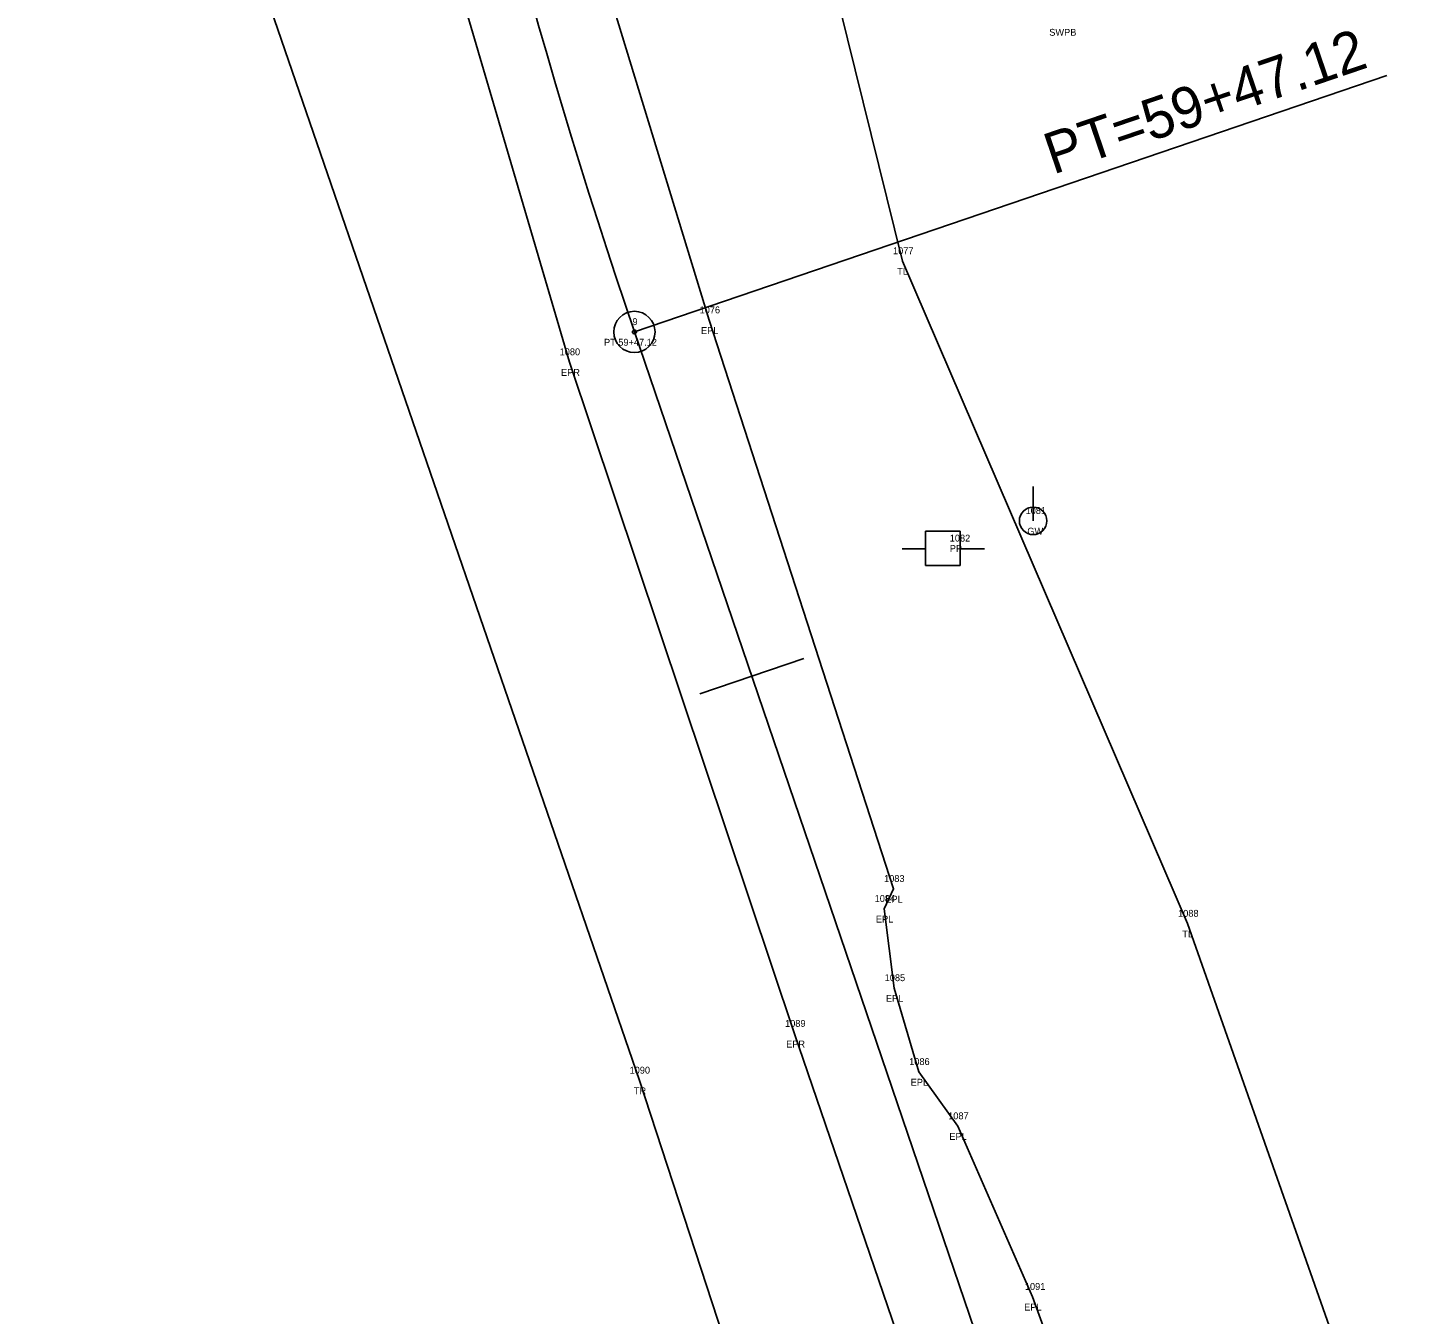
# Model space of a CAD drawing. Extents: x 2432632 to 2433497, y 684847 to 688233.
# Drawn here: x 2432885.8 to 2433086.5, y 686725.5 to 686912.6 of the extents above; entities that cross this region are included whole.
import ezdxf

# ---------------------------------------------------------------- set-up
doc = ezdxf.new("R2010")
doc.units = 0
for name, color, linetype in [('RD_EX_H2O_txCode', 7, 'Continuous'), ('RD_EX_Road', 7, 'Continuous'), ('RD_EX_Road_txCode', 7, 'Continuous'), ('RD_EX_UT', 7, 'Continuous'), ('RD_EX_UT_txCode', 7, 'Continuous'), ('RD_EX_VEG', 7, 'Continuous'), ('RD_EX_VEG_txCode', 7, 'Continuous'), ('RD_HC_Cl', 7, 'Continuous'), ('RD_HC_Data', 7, 'Continuous'), ('RD_HC_Data_Tic', 7, 'Continuous'), ('RD_HC_txCode', 7, 'Continuous'), ('RD_SMD_Locator', 7, 'Continuous')]:
    doc.layers.add(name, color=color, linetype=linetype)

msp = doc.modelspace()

# ---------------------------------------------------------------- linework, layer by layer
at = {"layer": 'RD_EX_Road'}
for points in [[(2433130.63, 688090.22), (2433103.18, 687988.73), (2433075.68, 687887.89), (2433049.83, 687790.75), (2433022.33, 687689.17), (2432994.76, 687586.82), (2432966.23, 687480.17), (2432943.15, 687390.42), (2432931.4, 687334.3), (2432921.83, 687273.88), (2432915.64, 687215.4), (2432913.86, 687159.12), (2432915.08, 687107.55), (2432919.97, 687053.4), (2432928.7, 686998.89), (2432946.77, 686924.59), (2432964.57, 686864), (2432997.3, 686766.34), (2433031.44, 686666.38), (2433066.06, 686565.78), (2433098.73, 686469.74)], [(2432966.49, 686930.23), (2432984.9, 686870.1), (2433011.7, 686787.41), (2433010.33, 686784.51), (2433011.78, 686772.99), (2433015.37, 686760.79), (2433021.02, 686752.9), (2433031.88, 686728.09), (2433052.76, 686670.56), (2433070.23, 686619.38), (2433072.02, 686607.31), (2433079.53, 686592.62), (2433082.99, 686582.32), (2433082.14, 686577.64), (2433086.96, 686563.7), (2433088.99, 686562.5), (2433099.45, 686534.09)]]:
    msp.add_lwpolyline(points, dxfattribs=at)
at = {"layer": 'RD_EX_UT'}
for p, q in [((2433031.98, 686840.92), (2433031.98, 686845.92)), ((2433021.35, 686839.42), (2433016.35, 686839.42)), ((2433016.35, 686839.42), (2433016.35, 686834.42)), ((2433021.35, 686834.42), (2433021.35, 686839.42)), ((2433012.92, 686836.86), (2433016.39, 686836.86)), ((2433021.28, 686836.86), (2433024.92, 686836.86)), ((2433016.35, 686834.42), (2433021.35, 686834.42))]:
    msp.add_line(p, q, dxfattribs=at)
msp.add_circle((2433031.98, 686840.92), 2, dxfattribs=at)
at = {"layer": 'RD_EX_VEG'}
for points in [[(2433112.43, 688094.61), (2433041.17, 687898.89), (2432988.9, 687699.78), (2432947.96, 687578.08), (2432935.9, 687556.87), (2432944.3, 687538.7), (2432913.88, 687397.98), (2432902.4, 687330.02), (2432885.78, 687157.56), (2432894.43, 687032.93), (2432918.07, 686924.4), (2432974.73, 686759.54), (2433073.82, 686456.42), (2433099.9, 686365.23), (2433115.47, 686257.21), (2433114.64, 686158.77), (2433095.68, 686092.78)], [(2433166.25, 688082.87), (2433111.93, 687876.69), (2433067.75, 687703.46), (2433065.05, 687678.03), (2433052.74, 687645.62), (2433005.45, 687469.88), (2432979.96, 687326.61), (2432966.8, 687267.34), (2432959.05, 687210.65), (2432959.25, 687071.62), (2432974.82, 687014.37), (2432998.13, 686938.9), (2433012.99, 686878.7), (2433054.45, 686782.35), (2433123.54, 686586.06), (2433129.82, 686546.35), (2433158.34, 686434.26), (2433192.79, 686274.67), (2433189.42, 686162.6), (2433197.4, 686074.41)]]:
    msp.add_lwpolyline(points, dxfattribs=at)
at = {"layer": 'RD_HC_Cl'}
msp.add_line((2432974.01, 686868.39), (2433123.37, 686430.08), dxfattribs=at)
msp.add_arc((2433840.56, 687163.67), 915.47, 164.98581, 198.81644, dxfattribs=at)
at = {"layer": 'RD_HC_Data'}
msp.add_line((2432974.01, 686868.39), (2433083.43, 686905.68), dxfattribs=at)
for radius in [3, 0.282]:
    msp.add_circle((2432974.01, 686868.39), radius, dxfattribs=at)
at = {"layer": 'RD_HC_Data_Tic'}
for q in [(2432998.64, 686820.92), (2432983.5, 686815.76)]:
    msp.add_line((2432991.07, 686818.34), q, dxfattribs=at)
at = {"layer": 'RD_SMD_Locator'}
for centre in [(2433012.99, 686878.7), (2432984.9, 686870.1), (2432974.01, 686868.39), (2432964.57, 686864), (2433011.7, 686787.41), (2433010.33, 686784.51), (2433054.45, 686782.35), (2433011.78, 686772.99), (2432997.3, 686766.34), (2432974.73, 686759.54), (2433015.37, 686760.79), (2433021.02, 686752.9), (2433031.88, 686728.09)]:
    msp.add_circle(centre, 0.001, dxfattribs=at)

# ---------------------------------------------------------------- texts
at = {"layer": 'RD_EX_H2O_txCode'}
msp.add_text('SWPB', height=1, dxfattribs=at).set_placement((2433034.33, 686911.46))
at = {"layer": 'RD_EX_Road_txCode'}
for s, p in [('1076', (2432983.49, 686871.1)), ('EPL', (2432983.69, 686868.1)), ('1080', (2432963.14, 686865)), ('EPR', (2432963.34, 686862)), ('1083', (2433010.31, 686788.41)), ('1084', (2433008.94, 686785.51)), ('EPL', (2433010.5, 686785.41)), ('EPL', (2433009.12, 686782.51)), ('1085', (2433010.4, 686773.99)), ('EPL', (2433010.58, 686770.99)), ('1089', (2432995.92, 686767.34)), ('EPR', (2432996.07, 686764.34)), ('1086', (2433013.96, 686761.79)), ('EPL', (2433014.17, 686758.79)), ('1087', (2433019.63, 686753.9)), ('EPL', (2433019.81, 686750.9)), ('1091', (2433030.78, 686729.09)), ('EPL', (2433030.68, 686726.09))]:
    msp.add_text(s, height=1, dxfattribs=at).set_placement(p)
at = {"layer": 'RD_EX_UT_txCode'}
for s, p in [('1081', (2433030.88, 686841.92)), ('GW', (2433031.14, 686838.92)), ('1082', (2433019.86, 686837.91)), ('PP', (2433019.86, 686836.41))]:
    msp.add_text(s, height=1, dxfattribs=at).set_placement(p)
at = {"layer": 'RD_EX_VEG_txCode'}
for s, p in [('1077', (2433011.61, 686879.7)), ('TL', (2433012.22, 686876.7)), ('1088', (2433053.06, 686783.35)), ('TL', (2433053.67, 686780.35)), ('1090', (2432973.31, 686760.54)), ('TR', (2432973.94, 686757.54))]:
    msp.add_text(s, height=1, dxfattribs=at).set_placement(p)
at = {"layer": 'RD_HC_Data'}
msp.add_text('PT=59+47.12', height=6, rotation=18.8164, dxfattribs=at).set_placement((2433034.89, 686891.25))
at = {"layer": 'RD_HC_txCode'}
for s, p in [('9', (2432973.73, 686869.39)), ('PT 59+47.12', (2432969.59, 686866.39))]:
    msp.add_text(s, height=1, dxfattribs=at).set_placement(p)

doc.saveas('drawing.dxf')
